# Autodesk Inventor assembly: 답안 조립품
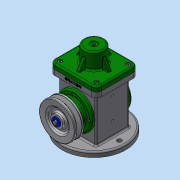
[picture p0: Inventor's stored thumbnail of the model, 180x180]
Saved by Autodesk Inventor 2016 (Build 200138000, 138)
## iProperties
Created: 2018-10
Part Number: 답안 조립품
Material: 일반
Document SubType Name: Assembly
Designer: Administrator
Author: Administrator
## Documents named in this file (18)
- C:\Users\Administrator\Desktop\481007V1047\답안 조립품.iam
- C:\Users\Administrator\Desktop\481007V1047\본체.ipt
- C:\Users\Administrator\Desktop\481007V1047\앞커버.ipt
- C:\Users\Administrator\Desktop\481007V1047\뒤커버.ipt
- C:\Users\Administrator\Desktop\481007V1047\덮개.ipt
- C:\Users\Administrator\Desktop\481007V1047\베어링 17 x 40 x 12.ipt
- C:\Users\Administrator\Desktop\481007V1047\편심축.ipt
- C:\Users\Administrator\Desktop\481007V1047\키 4 x 4 x 12.ipt
- C:\Users\Administrator\Desktop\481007V1047\슬라이더.ipt
- C:\Users\Administrator\Desktop\481007V1047\링크.ipt
- C:\Users\Administrator\Desktop\481007V1047\클레비스 핀 6 x 22.ipt
- 클레비스 핀 6 x 22.ipt
- C:\Users\Administrator\Desktop\481007V1047\E-링.ipt
- C:\Users\Administrator\Desktop\481007V1047\V-벨트풀리.ipt
- C:\Users\Administrator\Desktop\481007V1047\볼트 M4 x 10.ipt
- C:\Users\Administrator\Desktop\481007V1047\오일 실 17 30 8.ipt
- C:\Users\Administrator\Desktop\481007V1047\와셔 4x16.ipt
- C:\Users\Administrator\Desktop\481007V1047\볼트 M4 x 8.ipt
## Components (2 placed, 2 different names)
1. E-링:1
2. V-벨트풀리:1 — 각도:3
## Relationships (1: Angle 1)
- 각도:3 [Angle]: V-벨트풀리:1
